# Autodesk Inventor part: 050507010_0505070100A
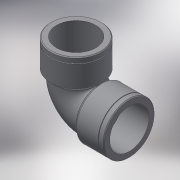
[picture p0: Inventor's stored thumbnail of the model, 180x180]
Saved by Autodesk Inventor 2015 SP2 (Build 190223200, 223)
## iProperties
Created: 2017-05
Part Number: 050507010_0505070100A
Material: Generic
Description: PLASSON THREADED ELBOW 1"-1"
Document SubType Name: Modeling
Designer: KIM
Density: 1 g/cm^3
Appearance: Default
Author: KIM
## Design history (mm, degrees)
derived "050507.ipt"
feature "Solid1::050507.ipt"
tag "TaggingFeature1"
body "Solid1"
other parameters: "d0" = 41, "d2" = 0.5, "d3" = 0.5, "d4" = 39.3783, "d5" = 30.291, "d6" = 21, "d7" = 135 deg, "d8" = 24.15, "d9" = 4.025, "d19" = 0.60582, "d27" = 21, "d30" = 27.2619, "d31" = 33.3201, "d33" = 90 deg, "d35" = 90 deg, "d36" = 90 deg, "d37" = 1.51455, "Rp_" = 30.291, "A_" = 41, "l_2" = 21
